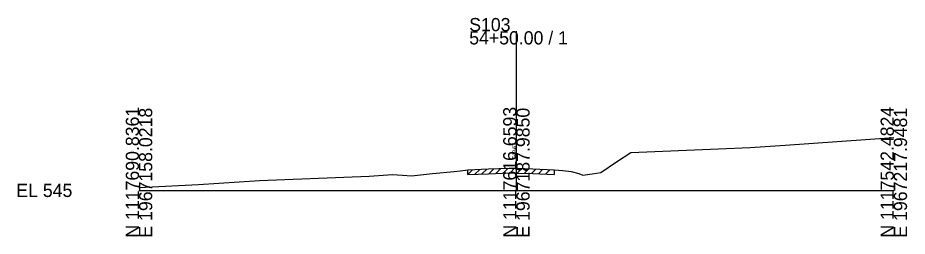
# Model space of a CAD drawing. Extents: x -26 to 163, y -10 to 24018.
# Drawn here: x -25.7 to 162.8, y 3990.3 to 4036.5 of the extents above; entities that cross this region are included whole.
import ezdxf

# ---------------------------------------------------------------- set-up
doc = ezdxf.new("R2010")
doc.units = 0
for name, color, linetype in [('RD_GPK_XS_Cell', 7, 'Continuous'), ('RD_XS_ExGround', 7, 'Continuous'), ('RD_XS_ExPaveRet', 7, 'Continuous'), ('RD_XS_TX_Elev_EX', 7, 'Continuous')]:
    doc.layers.add(name, color=color, linetype=linetype)

msp = doc.modelspace()

# ---------------------------------------------------------------- linework, layer by layer
at = {"layer": 'RD_GPK_XS_Cell'}
for p, q in [((80, 4000), (80, 4033.69)), ((0, 4000), (80, 4000)), ((80, 4000), (160, 4000))]:
    msp.add_line(p, q, dxfattribs=at)
at = {"layer": 'RD_XS_ExGround'}
msp.add_lwpolyline([(0, 4000.59), (12.58, 4001.24), (25.56, 4002.06), (36.29, 4002.55), (48.82, 4003.01), (53.73, 4003.35), (55.89, 4003.2), (57.73, 4003.08), (62.22, 4003.57), (66.79, 4004.02), (68.18, 4004.17), (69.67, 4004.33), (74.05, 4004.53), (78.48, 4004.73), (80, 4004.67), (83.51, 4004.54), (87.99, 4004.37), (89.83, 4004.2), (91.63, 4004.01), (93.23, 4003.58), (94.09, 4003.21), (96.08, 4003.5), (97.9, 4003.76), (101.23, 4006.06), (104.29, 4008.03), (122.85, 4008.79), (129.57, 4009.07), (136.95, 4009.58), (160, 4011.23)], dxfattribs=at)
at = {"layer": 'RD_XS_ExPaveRet'}
for p, q in [((71.17, 4003.4), (72.22, 4004.45)), ((72.67, 4003.47), (73.72, 4004.51)), ((74.17, 4003.53), (75.22, 4004.58)), ((75.67, 4003.6), (76.72, 4004.65)), ((77.17, 4003.67), (78.22, 4004.72)), ((78.67, 4003.72), (79.63, 4004.68)), ((80.17, 4003.67), (81.13, 4004.63)), ((81.67, 4003.61), (82.63, 4004.57)), ((83.17, 4003.55), (84.13, 4004.52)), ((84.67, 4003.5), (85.63, 4004.46)), ((69.67, 4003.33), (70.72, 4004.38)), ((69.67, 4003.33), (69.67, 4004.33)), ((69.67, 4003.33), (74.05, 4003.53)), ((74.05, 4003.53), (78.48, 4003.73)), ((78.48, 4003.73), (80, 4003.67)), ((80, 4003.67), (83.51, 4003.54)), ((83.51, 4003.54), (87.99, 4003.37)), ((86.17, 4003.44), (87.13, 4004.4)), ((87.99, 4004.37), (87.99, 4003.37))]:
    msp.add_line(p, q, dxfattribs=at)

# ---------------------------------------------------------------- texts
at = {"layer": 'RD_GPK_XS_Cell'}
for s, p in [('S103', (70, 4033.69)), ('54+50.00 / 1', (70, 4030.89)), ('EL 545', (-26, 3998.6))]:
    msp.add_text(s, height=2.8, dxfattribs=at).set_placement(p)
for s, p in [('N 1117690.8361', (0, 3990)), ('E 1967158.0218', (2.8, 3990)), ('N 1117616.6593', (80, 3990)), ('E 1967187.9850', (82.8, 3990)), ('N 1117542.4824', (160, 3990)), ('E 1967217.9481', (162.8, 3990))]:
    msp.add_text(s, height=2.8, rotation=90, dxfattribs=at).set_placement(p)
at = {"layer": 'RD_XS_TX_Elev_EX'}
msp.add_text('549.67', height=0.8, rotation=90, dxfattribs=at).set_placement((79.9, 4006.67))

doc.saveas('drawing.dxf')
